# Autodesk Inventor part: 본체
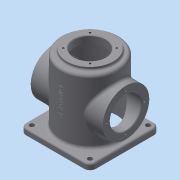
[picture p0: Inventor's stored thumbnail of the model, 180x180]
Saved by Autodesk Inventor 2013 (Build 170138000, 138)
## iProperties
Created: 2015-10
Part Number: 본체
Material: 일반
Document SubType Name: Modeling
Designer: dgall
Density: 1 g/cm^3
Author: dgall
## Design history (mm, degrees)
sketch "스케치1"
  geometry: L1 (-60, 60)-(60, 60); L2 (60, 60)-(60, -60); L3 (60, -60)-(-60, -60); L4 (-60, -60)-(-60, 60); L5 (-60, 60)-(60, -60); L6 (60, 60)-(-60, -60); C1 r 50 at (0, 0); C2 r 40 at (0, 0); C3 r 27 at (0, 0); 1 further point
  constraints: 12 end point, 3 centre point, 3 coincident, 2 midpoint, 2 parallel, 2 perpendicular, 1 horizontal
  dimensions: "d0" = 120 distance of L1.start L1.end; "d2" = 100 diameter of C1; "d3" = 40 radius of C2; "d4" = 27 radius of C3
extrude "돌출1" new body sketch "스케치1" distance "d5" = 10; taper "d6" = 0 deg
extrude "돌출2" join sketch "스케치1" distance "d7" = 110; taper "d8" = 0 deg
extrude "돌출3" join sketch "스케치1" distance "d9" = 115; taper "d10" = 0 deg
extrude "돌출5" cut sketch "스케치1" stored distance "d15" = 112; taper "d16" = 0 deg
sketch "스케치4"
  geometry: L1 (-60, -10)-(60, -10) reference; C1 r 40 at (0, 50); 1 further point
  constraints: 1 centre point, 1 vertical alignment
  dimensions: "d21" = 40 radius of C1; "d22" = 60 distance from line of L1 C1.centre
extrude "돌출7" join sketch "스케치4" stored distance "d23" = 124; taper "d24" = 0 deg
sketch "스케치5"
  geometry: C1 r 45 at (0, 0); 1 further point
  constraints: 1 centre point, 1 coincident
  dimensions: "d25" = 45 radius of C1
extrude "돌출8" cut sketch "스케치5" distance "d26" = 112; taper "d27" = 0 deg
hole "구멍1" diameter "d30" = 54; stored, may be unused: countersink angle "d34" = 90 deg, drill point angle "d36" = 118 deg; dims "d28" = 10, "d29" = 10, "d31" = 6, "d32" = 4, "d33" = 2, "d35" = 8
sketch "스케치6"
  geometry: C1 r 27 at (0, 0) reference; 2 further points
  constraints: 1 horizontal alignment
  dimensions: "d37" = 32.5 distance of point (32.5, 0) C1.centre
hole "구멍2" sketch "스케치6" at (32.5, 0) diameter "d38" = 3.242; stored, may be unused: countersink angle "d42" = 90 deg, drill point angle "d44" = 118 deg; dims "d39" = 8, "d40" = 4, "d41" = 2, "d43" = 10
chamfer "모따기1" distance "d48" = 3; stored, may be unused: second distance "d49" = 2, angle "d50" = 45 deg
chamfer "모따기2" distance "d51" = 1; stored, may be unused: second distance "d52" = 2, angle "d53" = 45 deg
fillet "모깎기1" dims "d54" = 10
fillet "모깎기2" dims "d55" = 5, "d56" = 3
sketch "스케치7"
  geometry: A1 r 7 centre (-50, -50) between (-57, -50) and (-50, -57) reference; A2 r 7 centre (50, -50) between (50, -57) and (57, -50) reference; A3 r 7 centre (50, 50) between (57, 50) and (50, 57) reference; A4 r 7 centre (-50, 50) between (-50, 57) and (-57, 50) reference
hole "구멍3" sketch "스케치7" at (-50, -50), (50, -50), (50, 50), (-50, 50) diameter "d57" = 8; stored, may be unused: countersink angle "d61" = 90 deg, drill point angle "d63" = 118 deg; dims "d58" = 8, "d59" = 4, "d60" = 2, "d62" = 10
node "작업 평면1"
sketch "스케치8"
  geometry: L1 (50, -10)-(-50, -10) reference; 2 further points
  constraints: 1 vertical alignment, 1 other
  dimensions: "d64" = 70 distance from line of L1 point (0, 60)
feature "엠보싱1" sketch "스케치8" dims "d0" = 120, "d65" = 0.5, "d66" = 0
sketch "스케치10"
  geometry: L1 (-75.861, 0)-(0, 0); L2 (0, 0)-(-63.373, 63.373); C1 r 40 at (0, 0) reference; C2 r 28 at (0, 0) reference; 1 further point
  constraints: 4 end point, 1 horizontal, 1 point on line
  dimensions: "d80" = 45 deg angle of L1 L2; "d81" = 32.5 distance of C1.centre point (-22.981, 22.981)
hole "구멍5" sketch "스케치10" at (-22.981, 22.981) diameter "d82" = 3.242; stored, may be unused: countersink angle "d86" = 90 deg, drill point angle "d88" = 118 deg; dims "d83" = 8, "d84" = 4, "d85" = 2, "d87" = 10
node "솔리드1"
pattern_circular "원형 패턴1" dims angle "d46" = 360 deg
mirror "대칭1"
pattern_circular "원형 패턴3" dims angle "d90" = 360 deg
